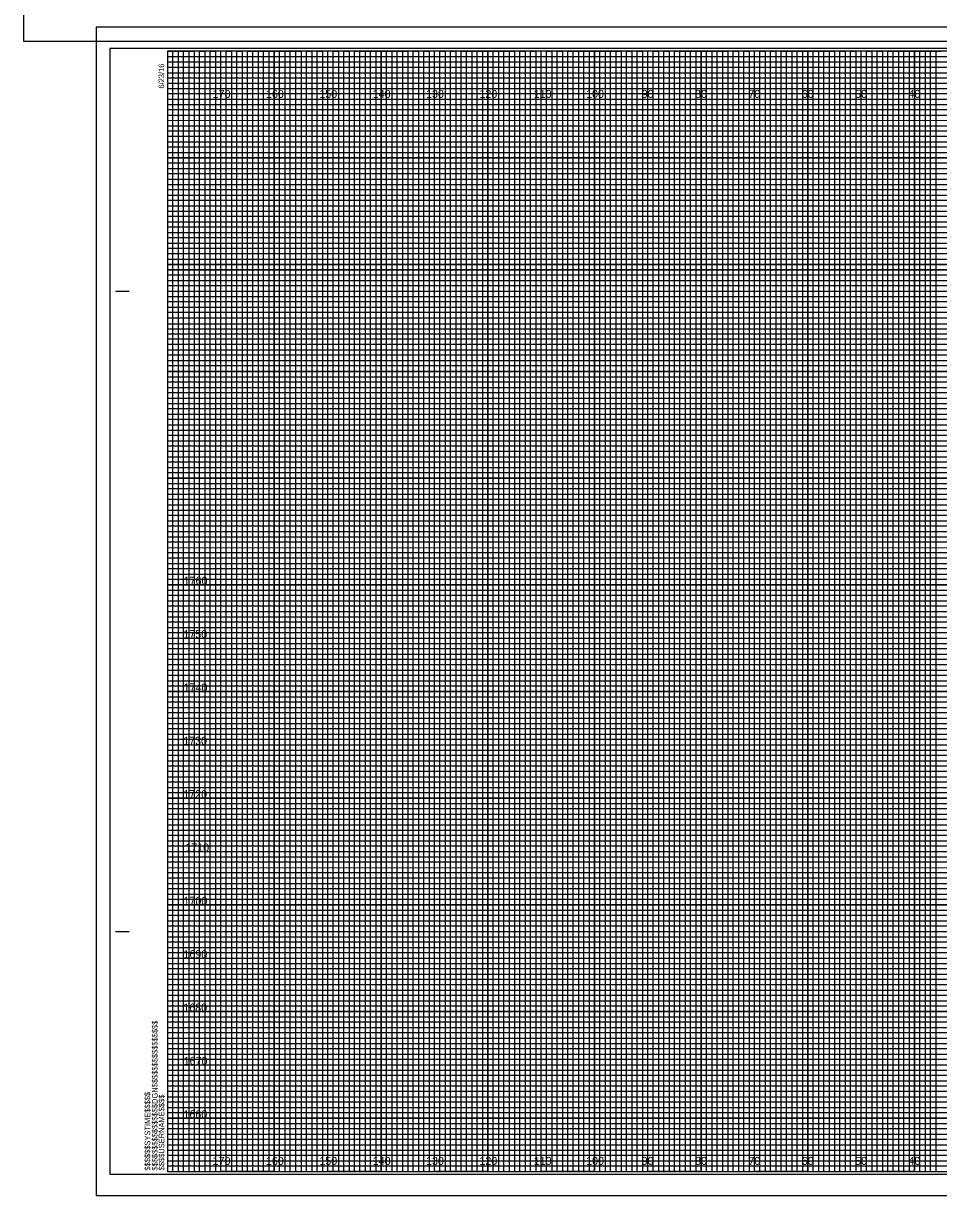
# Model space of a CAD drawing. Extents: x -13 to 1780, y -15 to 3284.
# Drawn here: x 726.7 to 898.2, y -4.8 to 214.9 of the extents above; entities that cross this region are included whole.
import ezdxf

# ---------------------------------------------------------------- set-up
doc = ezdxf.new("R2010")
doc.units = 0
for name, color, linetype in [('Prop Retaining Wall', 7, 'Continuous'), ('Prop SS Cut Line', 7, 'Continuous'), ('Prop SS Fill Line', 7, 'Continuous'), ('Prop SS Transition Line', 7, 'Continuous'), ('Prop XS Earthwork Shape', 7, 'Continuous'), ('Prop XS Noise Wall', 7, 'Continuous'), ('Prop XS Station Labels', 7, 'Continuous'), ('Raster_Level_0', 7, 'Continuous'), ('Scratch_Level_3', 7, 'Continuous'), ('Scratch_Level_7', 7, 'Continuous'), ('Typical Bridge Rail CELL', 7, 'Continuous')]:
    doc.layers.add(name, color=color, linetype=linetype)

msp = doc.modelspace()

# ---------------------------------------------------------------- linework, layer by layer
at = {"layer": 'Prop Retaining Wall'}
for p, q in [((743.88, 164.71), (746.38, 164.71)), ((743.98, 164.71), (746.48, 164.71)), ((743.88, 44.71), (746.38, 44.71)), ((743.98, 44.71), (746.48, 44.71)), ((753.68, -0.29), (753.68, -0.29)), ((753.68, -0.29), (753.68, -0.29)), ((753.68, -0.29), (753.68, -0.29)), ((753.68, -0.29), (753.68, -0.29)), ((753.68, -0.29), (753.68, -0.29)), ((753.68, -0.29), (753.68, -0.29)), ((753.68, -0.29), (753.68, -0.29))]:
    msp.add_line(p, q, dxfattribs=at)
msp.add_lwpolyline([(1073.68, 209.71), (753.68, 209.71), (753.68, -0.29), (1073.68, -0.29)], close=True, dxfattribs=at)
at = {"layer": 'Prop SS Cut Line'}
for points in [[(753.68, 209.71), (758.68, 209.71), (758.68, -0.29), (768.68, -0.29), (768.68, 209.71), (778.68, 209.71), (778.68, -0.29), (788.68, -0.29), (788.68, 209.71), (798.68, 209.71), (798.68, -0.29), (808.68, -0.29), (808.68, 209.71), (818.68, 209.71), (818.68, -0.29), (828.68, -0.29), (828.68, 209.71), (838.68, 209.71), (838.68, -0.29), (848.68, -0.29), (848.68, 209.71), (858.68, 209.71), (858.68, -0.29), (868.68, -0.29), (868.68, 209.71), (878.68, 209.71), (878.68, -0.29), (888.68, -0.29), (888.68, 209.71), (898.68, 209.71)], [(753.68, 204.71), (1028.68, 204.71)], [(753.68, 184.71), (1073.68, 184.71), (1073.68, 194.71), (753.68, 194.71)], [(753.68, 164.71), (1073.68, 164.71), (1073.68, 174.71), (753.68, 174.71)], [(753.68, 144.71), (1073.68, 144.71), (1073.68, 154.71), (753.68, 154.71)], [(753.68, 124.71), (1073.68, 124.71), (1073.68, 134.71), (753.68, 134.71)], [(753.68, 104.71), (1073.68, 104.71), (1073.68, 114.71), (753.68, 114.71)], [(753.68, 84.71), (1073.68, 84.71), (1073.68, 94.71), (753.68, 94.71)], [(753.68, 64.71), (1073.68, 64.71), (1073.68, 74.71), (753.68, 74.71)], [(753.68, 44.71), (1073.68, 44.71), (1073.68, 54.71), (753.68, 54.71)], [(753.68, 24.71), (1073.68, 24.71), (1073.68, 34.71), (753.68, 34.71)], [(753.68, 4.71), (1073.68, 4.71), (1073.68, 14.71), (753.68, 14.71)]]:
    msp.add_lwpolyline(points, dxfattribs=at)
at = {"layer": 'Prop SS Fill Line'}
for p, q in [((763.68, 209.71), (753.68, 209.71)), ((763.68, -0.29), (763.68, 209.71)), ((783.68, 209.71), (773.68, 209.71)), ((773.68, 209.71), (773.68, -0.29)), ((783.68, -0.29), (783.68, 209.71)), ((803.68, 209.71), (793.68, 209.71)), ((793.68, 209.71), (793.68, -0.29)), ((803.68, -0.29), (803.68, 209.71)), ((823.68, 209.71), (813.68, 209.71)), ((813.68, 209.71), (813.68, -0.29)), ((823.68, -0.29), (823.68, 209.71)), ((843.68, 209.71), (833.68, 209.71)), ((833.68, 209.71), (833.68, -0.29)), ((843.68, -0.29), (843.68, 209.71)), ((863.68, 209.71), (853.68, 209.71)), ((853.68, 209.71), (853.68, -0.29)), ((863.68, -0.29), (863.68, 209.71)), ((883.68, 209.71), (873.68, 209.71)), ((873.68, 209.71), (873.68, -0.29)), ((883.68, -0.29), (883.68, 209.71)), ((903.68, 209.71), (893.68, 209.71)), ((893.68, 209.71), (893.68, -0.29)), ((773.68, -0.29), (763.68, -0.29)), ((793.68, -0.29), (783.68, -0.29)), ((813.68, -0.29), (803.68, -0.29)), ((833.68, -0.29), (823.68, -0.29)), ((853.68, -0.29), (843.68, -0.29)), ((873.68, -0.29), (863.68, -0.29)), ((893.68, -0.29), (883.68, -0.29))]:
    msp.add_line(p, q, dxfattribs=at)
for points in [[(753.68, 199.71), (1073.68, 199.71), (1073.68, 189.71), (753.68, 189.71)], [(753.68, 179.71), (1073.68, 179.71), (1073.68, 169.71), (753.68, 169.71)], [(753.68, 159.71), (1073.68, 159.71), (1073.68, 149.71), (753.68, 149.71)], [(753.68, 139.71), (1073.68, 139.71), (1073.68, 129.71), (753.68, 129.71)], [(753.68, 119.71), (1073.68, 119.71), (1073.68, 109.71), (753.68, 109.71)], [(753.68, 99.71), (1073.68, 99.71), (1073.68, 89.71), (753.68, 89.71)], [(753.68, 79.71), (1073.68, 79.71), (1073.68, 69.71), (753.68, 69.71)], [(753.68, 59.71), (1073.68, 59.71), (1073.68, 49.71), (753.68, 49.71)], [(753.68, 39.71), (1073.68, 39.71), (1073.68, 29.71), (753.68, 29.71)], [(753.68, 19.71), (1073.68, 19.71), (1073.68, 9.71), (753.68, 9.71)]]:
    msp.add_lwpolyline(points, dxfattribs=at)
at = {"layer": 'Prop SS Transition Line'}
for p, q in [((753.68, 208.71), (1013.68, 208.71)), ((1013.68, 207.69), (753.68, 207.69)), ((753.68, 207.69), (753.68, 206.71)), ((753.68, 206.71), (1013.68, 206.71)), ((1013.68, 205.6), (753.68, 205.6)), ((753.68, 205.6), (753.68, 203.71)), ((753.68, 203.71), (1073.68, 203.71))]:
    msp.add_line(p, q, dxfattribs=at)
for points in [[(753.68, 202.71), (1023.68, 202.71), (1073.68, 202.71), (1073.68, 201.71), (753.68, 201.71)], [(753.68, 200.71), (1073.68, 200.71), (1073.68, 198.71), (753.68, 198.71)], [(753.68, 197.71), (1073.68, 197.71), (1073.68, 196.71), (753.68, 196.69)], [(753.68, 195.71), (1073.68, 195.71), (1073.68, 193.71), (753.68, 193.71)], [(753.68, 192.71), (1073.68, 192.71), (1073.68, 191.71), (753.68, 191.71)], [(753.68, 190.71), (1073.68, 190.71), (1073.68, 188.71), (753.68, 188.71)], [(753.68, 187.71), (1073.68, 187.71), (1073.68, 186.71), (753.68, 186.71)], [(753.68, 185.71), (1073.68, 185.71), (1073.68, 183.71), (753.68, 183.71)], [(753.68, 182.71), (1073.68, 182.71), (1073.68, 181.71), (753.68, 181.71)], [(753.68, 180.71), (1073.68, 180.71), (1073.68, 178.71), (753.68, 178.71)], [(753.68, 177.71), (1073.68, 177.71), (1073.68, 176.71), (753.68, 176.71)], [(753.68, 175.71), (1073.68, 175.71), (1073.68, 173.66), (1073.68, 172.71), (1073.68, 171.71), (753.68, 171.71)], [(753.68, 173.71), (1073.68, 173.71), (1073.68, 172.71), (753.68, 172.71)], [(753.68, 170.71), (1073.68, 170.71), (1073.68, 168.71), (753.68, 168.74)], [(753.68, 168.74), (1073.68, 168.71), (1073.68, 167.71), (753.68, 167.71)], [(753.68, 166.71), (1073.68, 166.71), (1073.68, 165.71), (753.68, 165.71)], [(753.68, 163.71), (1073.68, 163.71), (1073.68, 162.71), (753.68, 162.71)], [(753.68, 161.71), (1073.68, 161.71), (1073.68, 160.71), (753.68, 160.71)], [(753.61, 158.6), (1073.68, 158.6), (1073.68, 157.59), (753.61, 157.59)], [(753.68, 156.71), (1073.68, 156.71), (1073.68, 155.71), (753.68, 155.71)], [(753.68, 153.71), (1073.68, 153.71), (1073.68, 152.71), (753.68, 152.71)], [(753.68, 151.71), (1073.68, 151.71), (1073.68, 150.71), (753.68, 150.71)], [(753.68, 148.71), (1073.68, 148.71), (1073.68, 147.71), (753.68, 147.71)], [(753.68, 146.71), (1073.68, 146.71), (1073.68, 145.71), (753.68, 145.71)], [(753.68, 143.71), (1073.68, 143.71), (1073.68, 142.71), (753.68, 142.71)], [(753.68, 141.71), (1073.68, 141.71), (1073.68, 140.71), (753.68, 140.71)], [(753.68, 138.71), (1073.68, 138.71), (1073.67, 137.69), (753.68, 137.71)], [(753.68, 136.71), (1073.68, 136.71), (1073.68, 135.71), (753.68, 135.71)], [(753.68, 133.71), (1073.68, 133.71), (1073.68, 132.71), (753.68, 132.71)], [(753.68, 131.71), (1073.68, 131.71), (1073.68, 130.71), (753.68, 130.71)], [(753.68, 128.71), (1073.68, 128.71), (1073.68, 127.71), (753.68, 127.71)], [(753.68, 126.71), (1073.68, 126.71), (1073.68, 125.71), (753.68, 125.71)], [(753.68, 123.71), (1073.68, 123.71), (1073.68, 122.71), (753.68, 122.71)], [(753.68, 121.71), (1073.68, 121.71), (1073.68, 120.71), (753.68, 120.71)], [(753.68, 118.71), (1073.68, 118.71), (1073.68, 117.71), (753.68, 117.71)], [(753.68, 116.7), (1073.75, 116.62), (1073.68, 115.71), (753.68, 115.71)], [(753.68, 113.71), (1073.68, 113.71), (1073.68, 112.71), (753.68, 112.71)], [(753.68, 111.71), (1073.68, 111.71), (1073.68, 110.71), (753.68, 110.71)], [(753.68, 108.71), (1073.68, 108.71), (1073.68, 107.71), (753.68, 107.71)], [(753.68, 106.71), (1073.68, 106.71), (1073.68, 105.71), (753.68, 105.71)], [(753.68, 103.71), (1073.68, 103.71), (1073.68, 102.71), (753.68, 102.71)], [(753.68, 101.71), (1073.68, 101.71), (1073.68, 100.71), (753.68, 100.71)], [(753.68, 98.71), (1073.68, 98.71), (1073.68, 97.71), (753.68, 97.71)], [(753.68, 96.71), (1073.68, 96.71), (1073.68, 95.71), (753.68, 95.71)], [(753.68, 93.71), (1073.68, 93.71), (1073.68, 92.71), (753.68, 92.71)], [(753.68, 91.71), (1073.68, 91.71), (1073.68, 90.71), (753.68, 90.71)], [(753.68, 88.71), (1073.68, 88.71), (1073.68, 87.71), (753.68, 87.71)], [(753.68, 86.71), (1073.68, 86.71), (1073.68, 85.71), (753.68, 85.71)], [(753.68, 83.71), (1073.68, 83.71), (1073.68, 82.71), (753.68, 82.71)], [(753.68, 81.71), (1073.68, 81.71), (1073.68, 80.71), (753.68, 80.71)], [(753.68, 78.71), (1073.68, 78.71), (1073.67, 77.69), (753.68, 77.71)], [(753.68, 76.71), (1073.68, 76.71), (1073.68, 75.71), (753.68, 75.71)], [(753.68, 73.71), (1073.68, 73.71), (1073.68, 72.71), (753.68, 72.71)], [(753.68, 71.71), (1073.68, 71.71), (1073.68, 70.71), (753.68, 70.71)], [(753.68, 68.71), (1073.68, 68.71), (1073.68, 67.71), (753.68, 67.71)], [(753.68, 66.71), (1073.68, 66.71), (1073.68, 65.71), (753.68, 65.71)], [(753.68, 63.71), (1073.68, 63.71), (1073.68, 62.71), (753.68, 62.71)], [(753.68, 61.71), (1073.68, 61.71), (1073.68, 60.71), (753.68, 60.71)], [(753.68, 58.71), (1073.68, 58.71), (1073.68, 57.71), (753.68, 57.71)], [(753.68, 56.7), (1073.75, 56.62), (1073.68, 55.71), (753.68, 55.71)], [(753.68, 53.71), (1073.68, 53.71), (1073.68, 52.71), (753.68, 52.71)], [(753.68, 51.71), (1073.68, 51.71), (1073.68, 50.71), (753.68, 50.71)], [(753.68, 48.71), (1073.68, 48.71), (1073.68, 47.71), (753.68, 47.71)], [(753.68, 46.71), (1073.68, 46.71), (1073.68, 45.71), (753.68, 45.71)], [(753.68, 43.71), (1073.68, 43.71), (1073.68, 42.71), (753.68, 42.71)], [(753.68, 41.71), (1073.68, 41.71), (1073.68, 40.71), (753.68, 40.71)], [(753.68, 38.71), (1073.68, 38.71), (1073.68, 37.71), (753.68, 37.71)], [(753.68, 36.71), (1073.68, 36.71), (1073.68, 35.71), (753.68, 35.71)], [(753.68, 33.71), (1073.68, 33.71), (1073.68, 32.71), (753.68, 32.71)], [(753.68, 31.71), (1073.68, 31.71), (1073.68, 30.71), (753.68, 30.71)], [(753.68, 28.71), (1073.68, 28.71), (1073.68, 27.71), (753.68, 27.71)], [(753.68, 26.71), (1073.68, 26.71), (1073.68, 25.71), (753.68, 25.71)], [(753.68, 23.71), (1073.68, 23.71), (1073.68, 22.71), (753.68, 22.71)], [(753.68, 21.71), (1073.68, 21.71), (1073.68, 20.71), (753.68, 20.71)], [(753.68, 18.71), (1073.68, 18.71), (1073.68, 17.71), (753.68, 17.71)], [(753.68, 16.71), (1073.68, 16.71), (1073.68, 15.71), (753.68, 15.71)], [(753.68, 13.71), (1073.68, 13.71), (1073.68, 12.71), (753.68, 12.71)], [(753.68, 11.71), (1073.68, 11.71), (1073.68, 10.71), (753.68, 10.71)], [(753.68, 8.71), (1073.68, 8.71), (1073.68, 7.71), (753.68, 7.71)], [(753.68, 6.71), (1073.68, 6.71), (1073.68, 5.71), (753.68, 5.71)], [(753.68, 3.71), (1073.68, 3.71), (1073.68, 2.71), (753.68, 2.71)], [(753.68, 1.71), (1073.68, 1.71), (1073.68, 0.71), (753.68, 0.71)]]:
    msp.add_lwpolyline(points, dxfattribs=at)
at = {"layer": 'Prop XS Earthwork Shape'}
for points in [[(726.66, 211.62), (1063.36, 211.62), (1063.36, 430.62), (726.66, 430.62)], [(740.28, -4.79), (1076.98, -4.79), (1076.98, 214.21), (740.28, 214.21)]]:
    msp.add_lwpolyline(points, close=True, dxfattribs=at)
at = {"layer": 'Prop XS Noise Wall'}
for p, q in [((763.68, -0.29), (763.68, 209.71)), ((773.68, -0.29), (773.68, 209.71)), ((783.68, -0.29), (783.68, 209.71)), ((793.68, -0.29), (793.68, 209.71)), ((803.68, -0.29), (803.68, 209.71)), ((813.68, -0.29), (813.68, 209.71)), ((823.68, -0.29), (823.68, 209.71)), ((833.68, -0.29), (833.68, 209.71)), ((843.68, -0.29), (843.68, 209.71)), ((853.68, -0.29), (853.68, 209.71)), ((863.68, -0.29), (863.68, 209.71)), ((873.68, -0.29), (873.68, 209.71)), ((883.68, -0.29), (883.68, 209.71)), ((893.68, -0.29), (893.68, 209.71)), ((753.68, 199.71), (1073.68, 199.71)), ((753.68, 189.71), (1073.68, 189.71)), ((753.68, 179.71), (1073.68, 179.71)), ((753.68, 169.71), (1073.68, 169.71)), ((753.68, 159.71), (1073.68, 159.71)), ((753.68, 149.71), (1073.68, 149.71)), ((753.68, 139.71), (1073.68, 139.71)), ((753.68, 129.71), (1073.68, 129.71)), ((753.68, 119.71), (1073.68, 119.71)), ((753.68, 109.71), (1073.68, 109.71)), ((753.68, 99.71), (1073.68, 99.71)), ((753.68, 89.71), (1073.68, 89.71)), ((753.68, 79.71), (1073.68, 79.71)), ((753.68, 69.71), (1073.68, 69.71)), ((753.68, 59.71), (1073.68, 59.71)), ((753.68, 49.71), (1073.68, 49.71)), ((753.68, 39.71), (1073.68, 39.71)), ((753.68, 29.71), (1073.68, 29.71)), ((753.68, 19.71), (1073.68, 19.71)), ((753.68, 9.71), (1073.68, 9.71))]:
    msp.add_line(p, q, dxfattribs=at)
at = {"layer": 'Prop XS Station Labels'}
for p, q in [((726.66, 430.62), (726.66, 211.62)), ((1076.98, 214.21), (740.28, 214.21)), ((740.28, 214.21), (740.28, -4.79)), ((726.66, 211.62), (1063.36, 211.62)), ((740.28, -4.79), (1076.98, -4.79))]:
    msp.add_line(p, q, dxfattribs=at)
at = {"layer": 'Scratch_Level_7'}
msp.add_lwpolyline([(742.88, -0.79), (1076.08, -0.79), (1076.08, 210.21), (742.88, 210.21)], close=True, dxfattribs=at)
at = {"layer": 'Typical Bridge Rail CELL'}
for points in [[(753.68, -0.29), (754.68, -0.29), (754.68, 209.71), (755.68, 209.71), (755.68, -0.29)], [(755.68, -0.29), (756.68, -0.29), (756.68, 209.71), (757.68, 209.71), (757.68, -0.29)], [(758.68, -0.29), (759.68, -0.29), (759.68, 209.71), (760.68, 209.71), (760.68, -0.29)], [(760.68, -0.29), (761.68, -0.29), (761.68, 209.71), (762.68, 209.71), (762.68, -0.29)], [(763.68, -0.29), (764.68, -0.29), (764.68, 209.71), (765.68, 209.71), (765.68, -0.29)], [(765.68, -0.29), (766.68, -0.29), (766.68, 209.71), (767.68, 209.71), (767.68, -0.29)], [(768.68, -0.29), (769.68, -0.29), (769.68, 209.71), (770.68, 209.71), (770.68, -0.29)], [(770.68, -0.29), (771.68, -0.29), (771.68, 209.71), (772.68, 209.71), (772.68, -0.29)], [(773.68, -0.29), (774.68, -0.29), (774.68, 209.71), (775.68, 209.71), (775.68, -0.29)], [(775.68, -0.29), (776.68, -0.29), (776.68, 209.71), (777.68, 209.71), (777.68, -0.29)], [(778.68, -0.29), (779.68, -0.29), (779.68, 209.71), (780.68, 209.71), (780.68, -0.29)], [(780.68, -0.29), (781.68, -0.29), (781.68, 209.71), (782.68, 209.71), (782.68, -0.29)], [(783.68, -0.29), (784.68, -0.29), (784.68, 209.71), (785.68, 209.71), (785.68, -0.29)], [(785.68, -0.29), (786.68, -0.29), (786.68, 209.71), (787.68, 209.71), (787.68, -0.29)], [(788.68, -0.29), (789.68, -0.29), (789.68, 209.71), (790.68, 209.71), (790.68, -0.29)], [(790.68, -0.29), (791.68, -0.29), (791.68, 209.71), (792.68, 209.71), (792.68, -0.29)], [(793.68, -0.29), (794.68, -0.29), (794.68, 209.71), (795.68, 209.71), (795.68, -0.29)], [(795.68, -0.29), (796.68, -0.29), (796.68, 209.71), (797.68, 209.71), (797.68, -0.29)], [(798.68, -0.29), (799.68, -0.29), (799.68, 209.71), (800.68, 209.71), (800.68, -0.29)], [(800.68, -0.29), (801.68, -0.29), (801.68, 209.71), (802.68, 209.71), (802.68, -0.29)], [(803.68, -0.29), (804.68, -0.29), (804.68, 209.71), (805.68, 209.71), (805.68, -0.29)], [(805.68, -0.29), (806.68, -0.29), (806.68, 209.71), (807.68, 209.71), (807.68, -0.29)], [(808.68, -0.29), (809.68, -0.29), (809.68, 209.71), (810.68, 209.71), (810.68, -0.29)], [(810.68, -0.29), (811.68, -0.29), (811.68, 209.71), (812.68, 209.71), (812.68, -0.29)], [(813.68, -0.29), (814.68, -0.29), (814.68, 209.71), (815.68, 209.71), (815.68, -0.29)], [(815.68, -0.29), (816.68, -0.29), (816.68, 209.71), (817.68, 209.71), (817.68, -0.29)], [(818.68, -0.29), (819.68, -0.29), (819.68, 209.71), (820.68, 209.71), (820.68, -0.29)], [(820.68, -0.29), (821.68, -0.29), (821.68, 209.71), (822.68, 209.71), (822.68, -0.29)], [(823.68, -0.29), (824.68, -0.29), (824.68, 209.71), (825.68, 209.71), (825.68, -0.29)], [(825.68, -0.29), (826.68, -0.29), (826.68, 209.71), (827.68, 209.71), (827.68, -0.29)], [(828.68, -0.29), (829.68, -0.29), (829.68, 209.71), (830.68, 209.71), (830.68, -0.29)], [(830.68, -0.29), (831.68, -0.29), (831.68, 209.71), (832.68, 209.71), (832.68, -0.29)], [(833.68, -0.29), (834.68, -0.29), (834.68, 209.71), (835.68, 209.71), (835.68, -0.29)], [(835.68, -0.29), (836.68, -0.29), (836.68, 209.71), (837.68, 209.71), (837.68, -0.29)], [(838.68, -0.29), (839.68, -0.29), (839.68, 209.71), (840.68, 209.71), (840.68, -0.29)], [(840.68, -0.29), (841.68, -0.29), (841.68, 209.71), (842.68, 209.71), (842.68, -0.29)], [(843.68, -0.29), (844.68, -0.29), (844.68, 209.71), (845.68, 209.71), (845.68, -0.29)], [(845.68, -0.29), (846.68, -0.29), (846.68, 209.71), (847.68, 209.71), (847.68, -0.29)], [(848.68, -0.29), (849.68, -0.29), (849.68, 209.71), (850.68, 209.71), (850.68, -0.29)], [(850.68, -0.29), (851.68, -0.29), (851.68, 209.71), (852.68, 209.71), (852.68, -0.29)], [(853.68, -0.29), (854.68, -0.29), (854.68, 209.71), (855.68, 209.71), (855.68, -0.29)], [(855.68, -0.29), (856.68, -0.29), (856.68, 209.71), (857.68, 209.71), (857.68, -0.29)], [(858.68, -0.29), (859.68, -0.29), (859.68, 209.71), (860.68, 209.71), (860.68, -0.29)], [(860.68, -0.29), (861.68, -0.29), (861.68, 209.71), (862.68, 209.71), (862.68, -0.29)], [(863.68, -0.29), (864.68, -0.29), (864.68, 209.71), (865.68, 209.71), (865.68, -0.29)], [(865.68, -0.29), (866.68, -0.29), (866.68, 209.71), (867.68, 209.71), (867.68, -0.29)], [(868.68, -0.29), (869.68, -0.29), (869.68, 209.71), (870.68, 209.71), (870.68, -0.29)], [(870.68, -0.29), (871.68, -0.29), (871.68, 209.71), (872.68, 209.71), (872.68, -0.29)], [(873.68, -0.29), (874.68, -0.29), (874.68, 209.71), (875.68, 209.71), (875.68, -0.29)], [(875.68, -0.29), (876.68, -0.29), (876.68, 209.71), (877.68, 209.71), (877.68, -0.29)], [(878.68, -0.29), (879.68, -0.29), (879.68, 209.71), (880.68, 209.71), (880.68, -0.29)], [(880.68, -0.29), (881.68, -0.29), (881.68, 209.71), (882.68, 209.71), (882.68, -0.29)], [(883.68, -0.29), (884.68, -0.29), (884.68, 209.71), (885.68, 209.71), (885.68, -0.29)], [(885.68, -0.29), (886.68, -0.29), (886.68, 209.71), (887.68, 209.71), (887.68, -0.29)], [(888.68, -0.29), (889.68, -0.29), (889.68, 209.71), (890.68, 209.71), (890.68, -0.29)], [(890.68, -0.29), (891.68, -0.29), (891.68, 209.71), (892.68, 209.71), (892.68, -0.29)], [(893.68, -0.29), (894.68, -0.29), (894.68, 209.71), (895.68, 209.71), (895.68, -0.29)], [(895.68, -0.29), (896.68, -0.29), (896.68, 209.71), (897.68, 209.71), (897.68, -0.29)]]:
    msp.add_lwpolyline(points, dxfattribs=at)

# ---------------------------------------------------------------- texts
at = {"layer": 'Prop Retaining Wall'}
for s, p in [('6/23/16', (753.03, 202.71)), ('$$$$$$$$$$$$$$$$DGN$$$$$$$$$$$$$$$$', (751.8, -0.11)), ('$$$$$$SYSTIME$$$$$', (750.42, -0.11)), ('$$$$USERNAME$$$$', (753.06, -0.06))]:
    msp.add_text(s, height=1.05, rotation=90, dxfattribs=at).set_placement(p)
at = {"layer": 'Raster_Level_0'}
for s, p in [('170', (762.12, 200.96)), ('160', (772.12, 200.96)), ('150', (782.12, 200.96)), ('140', (792.12, 200.96)), ('130', (802.12, 200.96)), ('120', (812.12, 200.96)), ('110', (822.3, 200.96)), ('100', (832.12, 200.96)), ('90', (842.54, 200.96)), ('80', (852.54, 200.96)), ('70', (862.54, 200.96)), ('60', (872.54, 200.96)), ('50', (882.54, 200.96)), ('40', (892.54, 200.96)), ('170', (762.12, 0.96)), ('160', (772.12, 0.96)), ('150', (782.12, 0.96)), ('140', (792.12, 0.96)), ('130', (802.12, 0.96)), ('120', (812.12, 0.96)), ('110', (822.3, 0.96)), ('100', (832.12, 0.96)), ('90', (842.54, 0.96)), ('80', (852.54, 0.96)), ('70', (862.54, 0.96)), ('60', (872.54, 0.96)), ('50', (882.54, 0.96)), ('40', (892.54, 0.96))]:
    msp.add_text(s, height=1.5, dxfattribs=at).set_placement(p)
at = {"layer": 'Scratch_Level_3'}
for s, p in [('1760', (756.68, 109.71)), ('1750', (756.64, 99.71)), ('1740', (756.68, 89.71)), ('1730', (756.6, 79.71)), ('1720', (756.61, 69.71)), ('1710', (756.99, 59.71)), ('1700', (756.66, 49.71)), ('1690', (756.65, 39.71)), ('1680', (756.62, 29.71)), ('1670', (756.68, 19.71)), ('1660', (756.65, 9.71))]:
    msp.add_text(s, height=1.5, dxfattribs=at).set_placement(p)

doc.saveas('drawing.dxf')
